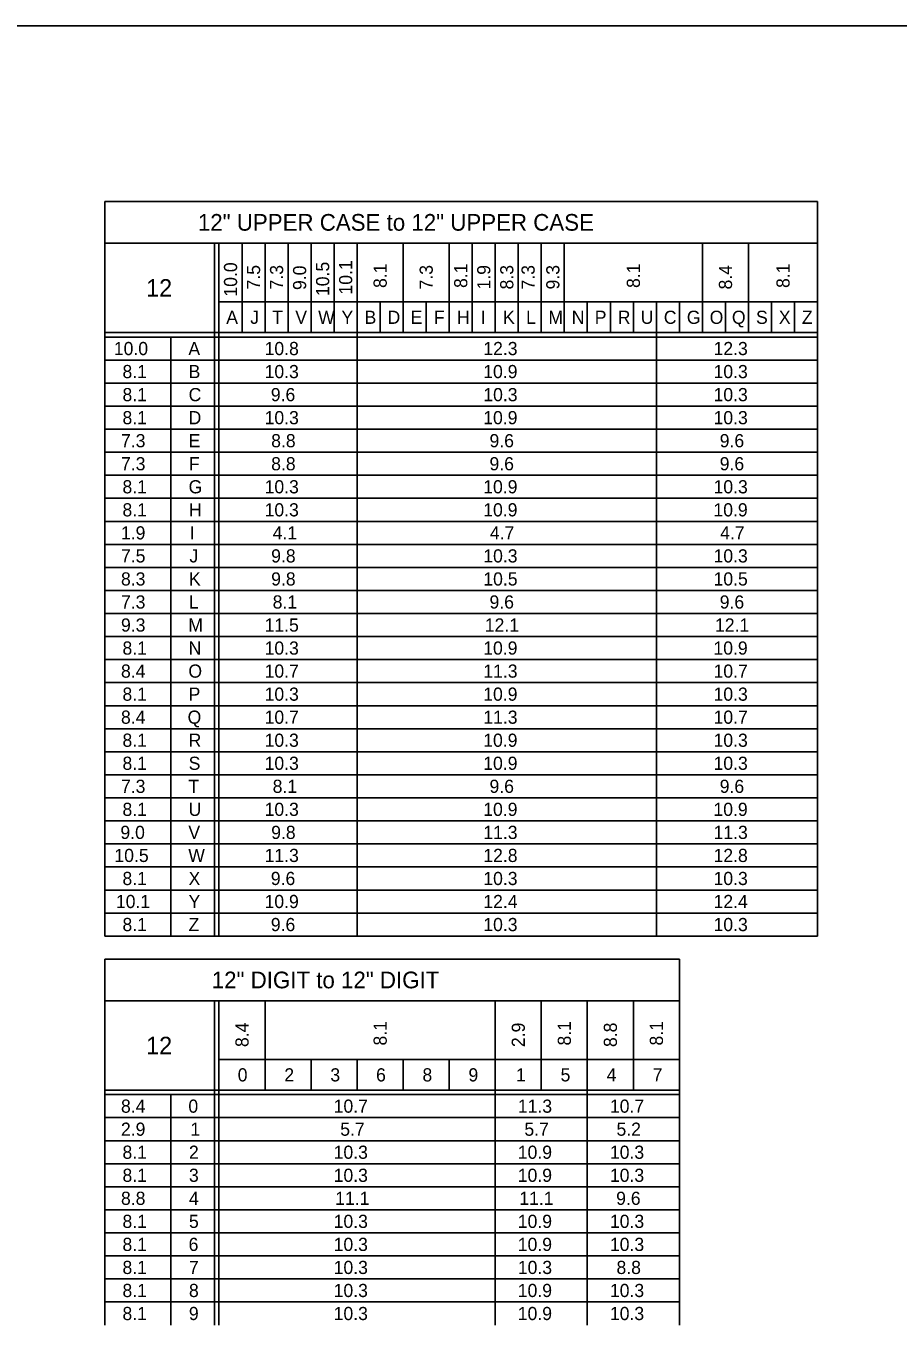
# Model space of a CAD drawing. Extents: x 638421 to 641849, y 297270 to 299646.
# Drawn here: x 640342.2 to 640541.1, y 298146.6 to 298442.6 of the extents above; entities that cross this region are included whole.
import ezdxf

# ---------------------------------------------------------------- set-up
doc = ezdxf.new("R2010")
doc.units = 0
doc.layers.add('1', color=7, linetype='Continuous')
doc.layers.add('2', color=7, linetype='Continuous')

msp = doc.modelspace()

# ---------------------------------------------------------------- linework, layer by layer
at = {"layer": '1'}
msp.add_line((640143.31, 298442.63), (640929.31, 298442.63), dxfattribs=at)
at = {"layer": '2'}
for p, q in [((640522.71, 298402.63), (640360.21, 298402.63)), ((640360.21, 298402.63), (640360.21, 298235.25)), ((640522.71, 298402.63), (640522.71, 298235.25)), ((640360.21, 298393.13), (640522.71, 298393.13)), ((640385.21, 298393.13), (640385.21, 298235.25)), ((640386.21, 298393.13), (640386.21, 298235.25)), ((640391.46, 298393.13), (640391.46, 298372.75)), ((640396.71, 298393.13), (640396.71, 298372.75)), ((640401.96, 298393.13), (640401.96, 298372.75)), ((640407.21, 298393.13), (640407.21, 298372.75)), ((640412.46, 298393.13), (640412.46, 298372.75)), ((640417.71, 298393.13), (640417.71, 298235.25)), ((640428.21, 298393.13), (640428.21, 298372.75)), ((640438.71, 298393.13), (640438.71, 298372.75)), ((640443.96, 298393.13), (640443.96, 298372.75)), ((640449.21, 298393.13), (640449.21, 298372.75)), ((640454.46, 298393.13), (640454.46, 298372.75)), ((640459.71, 298393.13), (640459.71, 298372.75)), ((640464.96, 298393.13), (640464.96, 298372.75)), ((640496.46, 298393.13), (640496.46, 298372.75)), ((640506.96, 298393.13), (640506.96, 298372.75)), ((640386.21, 298379.75), (640522.71, 298379.75)), ((640422.96, 298379.75), (640422.96, 298372.75)), ((640433.46, 298379.75), (640433.46, 298372.75)), ((640470.21, 298379.75), (640470.21, 298372.75)), ((640475.46, 298379.75), (640475.46, 298372.75)), ((640480.71, 298379.75), (640480.71, 298372.75)), ((640480.71, 298379.75), (640480.71, 298372.75)), ((640485.96, 298379.75), (640485.96, 298235.25)), ((640491.21, 298379.75), (640491.21, 298372.75)), ((640501.71, 298379.75), (640501.71, 298372.75)), ((640512.21, 298379.75), (640512.21, 298372.75)), ((640517.46, 298379.75), (640517.46, 298372.75)), ((640522.71, 298372.75), (640360.21, 298372.75)), ((640522.71, 298371.75), (640360.21, 298371.75)), ((640375.21, 298371.75), (640375.21, 298235.25)), ((640522.71, 298366.5), (640360.21, 298366.5)), ((640522.71, 298361.25), (640360.21, 298361.25)), ((640522.71, 298356), (640360.21, 298356)), ((640522.71, 298350.75), (640360.21, 298350.75)), ((640522.71, 298345.5), (640360.21, 298345.5)), ((640522.71, 298340.25), (640360.21, 298340.25)), ((640522.71, 298335), (640360.21, 298335)), ((640522.71, 298329.75), (640360.21, 298329.75)), ((640522.71, 298324.5), (640360.21, 298324.5)), ((640522.71, 298319.25), (640360.21, 298319.25)), ((640522.71, 298314), (640360.21, 298314)), ((640522.71, 298308.75), (640360.21, 298308.75)), ((640522.71, 298303.5), (640360.21, 298303.5)), ((640522.71, 298298.25), (640360.21, 298298.25)), ((640522.71, 298293), (640360.21, 298293)), ((640522.71, 298287.75), (640360.21, 298287.75)), ((640522.71, 298282.5), (640360.21, 298282.5)), ((640522.71, 298277.25), (640360.21, 298277.25)), ((640522.71, 298272), (640360.21, 298272)), ((640522.71, 298266.75), (640360.21, 298266.75)), ((640522.71, 298261.5), (640360.21, 298261.5)), ((640522.71, 298256.25), (640360.21, 298256.25)), ((640522.71, 298251), (640360.21, 298251)), ((640522.71, 298245.75), (640360.21, 298245.75)), ((640522.71, 298240.5), (640360.21, 298240.5)), ((640360.21, 298235.25), (640360.21, 298235.25)), ((640360.21, 298235.25), (640522.71, 298235.25)), ((640491.21, 298230), (640360.21, 298230)), ((640360.21, 298230), (640360.21, 298146.63)), ((640491.21, 298146.63), (640491.21, 298230)), ((640360.21, 298220.5), (640491.21, 298220.5)), ((640385.21, 298220.5), (640385.21, 298146.63)), ((640386.21, 298220.5), (640386.21, 298146.63)), ((640396.71, 298220.5), (640396.71, 298200.13)), ((640449.21, 298220.5), (640449.21, 298146.63)), ((640459.71, 298220.5), (640459.71, 298200.13)), ((640470.21, 298220.5), (640470.21, 298146.63)), ((640480.71, 298220.5), (640480.71, 298200.13)), ((640386.21, 298207.13), (640491.21, 298207.13)), ((640407.21, 298207.13), (640407.21, 298200.13)), ((640417.71, 298207.13), (640417.71, 298200.13)), ((640428.21, 298207.13), (640428.21, 298200.13)), ((640438.71, 298207.13), (640438.71, 298200.13)), ((640491.21, 298200.13), (640360.21, 298200.13)), ((640491.21, 298199.13), (640360.21, 298199.13)), ((640375.21, 298199.13), (640375.21, 298146.63)), ((640491.21, 298193.88), (640360.21, 298193.88)), ((640491.21, 298188.63), (640360.21, 298188.63)), ((640491.21, 298183.38), (640360.21, 298183.38)), ((640491.21, 298178.13), (640360.21, 298178.13)), ((640491.21, 298172.88), (640360.21, 298172.88)), ((640491.21, 298167.63), (640360.21, 298167.63)), ((640491.21, 298162.38), (640360.21, 298162.38)), ((640491.21, 298157.13), (640360.21, 298157.13)), ((640491.21, 298151.88), (640360.21, 298151.88))]:
    msp.add_line(p, q, dxfattribs=at)

# ---------------------------------------------------------------- texts
for s, height, p in [('12" UPPER CASE to 12" UPPER CASE', 3.8, (640381.4, 298395.98)), ('12', 4, (640369.58, 298380.94)), ('A', 3, (640387.86, 298374.75)), ('J', 3, (640393.34, 298374.75)), ('T', 3, (640398.34, 298374.75)), ('V', 3, (640403.61, 298374.75)), ('W', 3, (640408.83, 298374.75)), ('Y', 3, (640414.14, 298374.75)), ('B', 3, (640419.4, 298374.75)), ('D', 3, (640424.65, 298374.75)), ('E', 3, (640429.92, 298374.75)), ('F', 3, (640435.22, 298374.75)), ('H', 3, (640440.49, 298374.75)), ('I', 3, (640445.9, 298374.75)), ('K', 3, (640450.99, 298374.75)), ('L', 3, (640456.24, 298374.75)), ('M', 3, (640461.33, 298374.75)), ('N', 3, (640466.65, 298374.75)), ('P', 3, (640471.9, 298374.75)), ('R', 3, (640477.15, 298374.75)), ('U', 3, (640482.39, 298374.75)), ('C', 3, (640487.65, 298374.75)), ('G', 3, (640492.9, 298374.75)), ('O', 3, (640498.11, 298374.75)), ('Q', 3, (640503.18, 298374.75)), ('S', 3, (640508.67, 298374.75)), ('X', 3, (640513.89, 298374.75)), ('Z', 3, (640519.15, 298374.75)), ('10.0', 3, (640362.23, 298367.63)), ('A', 3, (640379.23, 298367.63)), ('10.8', 3, (640396.61, 298367.63)), ('12.3', 3, (640446.49, 298367.63)), ('12.3', 3, (640498.99, 298367.63)), ('8.1', 3, (640364.2, 298362.38)), ('B', 3, (640379.28, 298362.38)), ('10.3', 3, (640396.61, 298362.38)), ('10.9', 3, (640446.47, 298362.38)), ('10.3', 3, (640498.99, 298362.38)), ('8.1', 3, (640364.2, 298357.13)), ('C', 3, (640379.28, 298357.13)), ('9.6', 3, (640398.03, 298357.13)), ('10.3', 3, (640446.49, 298357.13)), ('10.3', 3, (640498.99, 298357.13)), ('8.1', 3, (640364.2, 298351.88)), ('D', 3, (640379.28, 298351.88)), ('10.3', 3, (640396.61, 298351.88)), ('10.9', 3, (640446.47, 298351.88)), ('10.3', 3, (640498.99, 298351.88)), ('7.3', 3, (640363.86, 298346.63)), ('E', 3, (640379.29, 298346.63)), ('8.8', 3, (640398.11, 298346.63)), ('9.6', 3, (640447.9, 298346.63)), ('9.6', 3, (640500.4, 298346.63)), ('7.3', 3, (640363.86, 298341.38)), ('F', 3, (640379.35, 298341.38)), ('8.8', 3, (640398.11, 298341.38)), ('9.6', 3, (640447.9, 298341.38)), ('9.6', 3, (640500.4, 298341.38)), ('8.1', 3, (640364.2, 298336.13)), ('G', 3, (640379.28, 298336.13)), ('10.3', 3, (640396.61, 298336.13)), ('10.9', 3, (640446.47, 298336.13)), ('10.3', 3, (640498.99, 298336.13)), ('8.1', 3, (640364.2, 298330.88)), ('H', 3, (640379.36, 298330.88)), ('10.3', 3, (640396.61, 298330.88)), ('10.9', 3, (640446.47, 298330.88)), ('10.9', 3, (640498.97, 298330.88)), ('1.9', 3, (640363.85, 298325.63)), ('I', 3, (640379.53, 298325.63)), ('4.1', 3, (640398.45, 298325.63)), ('4.7', 3, (640447.99, 298325.63)), ('4.7', 3, (640500.49, 298325.63)), ('7.5', 3, (640363.86, 298320.38)), ('J', 3, (640379.47, 298320.38)), ('9.8', 3, (640398.11, 298320.38)), ('10.3', 3, (640446.49, 298320.38)), ('10.3', 3, (640498.99, 298320.38)), ('8.3', 3, (640363.86, 298315.13)), ('K', 3, (640379.36, 298315.13)), ('9.8', 3, (640398.11, 298315.13)), ('10.5', 3, (640446.49, 298315.13)), ('10.5', 3, (640498.99, 298315.13)), ('7.3', 3, (640363.86, 298309.88)), ('L', 3, (640379.36, 298309.88)), ('8.1', 3, (640398.45, 298309.88)), ('9.6', 3, (640447.9, 298309.88)), ('9.6', 3, (640500.4, 298309.88)), ('9.3', 3, (640363.86, 298304.63)), ('M', 3, (640379.21, 298304.63)), ('11.5', 3, (640396.61, 298304.63)), ('12.1', 3, (640446.83, 298304.63)), ('12.1', 3, (640499.33, 298304.63)), ('8.1', 3, (640364.2, 298299.38)), ('N', 3, (640379.28, 298299.38)), ('10.3', 3, (640396.61, 298299.38)), ('10.9', 3, (640446.47, 298299.38)), ('10.9', 3, (640498.97, 298299.38)), ('8.4', 3, (640363.86, 298294.13)), ('O', 3, (640379.23, 298294.13)), ('10.7', 3, (640396.61, 298294.13)), ('11.3', 3, (640446.49, 298294.13)), ('10.7', 3, (640498.99, 298294.13)), ('8.1', 3, (640364.2, 298288.88)), ('P', 3, (640379.28, 298288.88)), ('10.3', 3, (640396.61, 298288.88)), ('10.9', 3, (640446.47, 298288.88)), ('10.3', 3, (640498.99, 298288.88)), ('8.4', 3, (640363.86, 298283.63)), ('Q', 3, (640379.05, 298283.63)), ('10.7', 3, (640396.61, 298283.63)), ('11.3', 3, (640446.49, 298283.63)), ('10.7', 3, (640498.99, 298283.63)), ('8.1', 3, (640364.2, 298278.38)), ('R', 3, (640379.28, 298278.38)), ('10.3', 3, (640396.61, 298278.38)), ('10.9', 3, (640446.47, 298278.38)), ('10.3', 3, (640498.99, 298278.38)), ('8.1', 3, (640364.2, 298273.13)), ('S', 3, (640379.29, 298273.13)), ('10.3', 3, (640396.61, 298273.13)), ('10.9', 3, (640446.47, 298273.13)), ('10.3', 3, (640498.99, 298273.13)), ('7.3', 3, (640363.86, 298267.88)), ('T', 3, (640379.22, 298267.88)), ('8.1', 3, (640398.45, 298267.88)), ('9.6', 3, (640447.9, 298267.88)), ('9.6', 3, (640500.4, 298267.88)), ('8.1', 3, (640364.2, 298262.63)), ('U', 3, (640379.27, 298262.63)), ('10.3', 3, (640396.61, 298262.63)), ('10.9', 3, (640446.47, 298262.63)), ('10.9', 3, (640498.97, 298262.63)), ('9.0', 3, (640363.73, 298257.38)), ('V', 3, (640379.23, 298257.38)), ('9.8', 3, (640398.11, 298257.38)), ('11.3', 3, (640446.49, 298257.38)), ('11.3', 3, (640498.99, 298257.38)), ('10.5', 3, (640362.36, 298252.13)), ('W', 3, (640379.21, 298252.13)), ('11.3', 3, (640396.61, 298252.13)), ('12.8', 3, (640446.49, 298252.13)), ('12.8', 3, (640498.99, 298252.13)), ('8.1', 3, (640364.2, 298246.88)), ('X', 3, (640379.27, 298246.88)), ('9.6', 3, (640398.03, 298246.88)), ('10.3', 3, (640446.49, 298246.88)), ('10.3', 3, (640498.99, 298246.88)), ('10.1', 3, (640362.7, 298241.63)), ('Y', 3, (640379.27, 298241.63)), ('10.9', 3, (640396.6, 298241.63)), ('12.4', 3, (640446.49, 298241.63)), ('12.4', 3, (640498.99, 298241.63)), ('8.1', 3, (640364.2, 298236.38)), ('Z', 3, (640379.28, 298236.38)), ('9.6', 3, (640398.03, 298236.38)), ('10.3', 3, (640446.49, 298236.38)), ('10.3', 3, (640498.99, 298236.38)), ('12" DIGIT to 12" DIGIT', 3.8, (640384.56, 298223.35)), ('12', 4, (640369.58, 298208.31)), ('0', 3, (640390.48, 298202.13)), ('2', 3, (640401.11, 298202.13)), ('3', 3, (640411.61, 298202.13)), ('6', 3, (640422.03, 298202.13)), ('8', 3, (640432.61, 298202.13)), ('9', 3, (640443.1, 298202.13)), ('1', 3, (640453.95, 298202.13)), ('5', 3, (640464.11, 298202.13)), ('4', 3, (640474.61, 298202.13)), ('7', 3, (640485.11, 298202.13)), ('8.4', 3, (640363.86, 298195)), ('0', 3, (640379.23, 298195)), ('10.7', 3, (640412.36, 298195)), ('11.3', 3, (640454.36, 298195)), ('10.7', 3, (640475.36, 298195)), ('2.9', 3, (640363.85, 298189.75)), ('1', 3, (640379.7, 298189.75)), ('5.7', 3, (640413.86, 298189.75)), ('5.7', 3, (640455.86, 298189.75)), ('5.2', 3, (640476.86, 298189.75)), ('8.1', 3, (640364.2, 298184.5)), ('2', 3, (640379.36, 298184.5)), ('10.3', 3, (640412.36, 298184.5)), ('10.9', 3, (640454.35, 298184.5)), ('10.3', 3, (640475.36, 298184.5)), ('8.1', 3, (640364.2, 298179.25)), ('3', 3, (640379.36, 298179.25)), ('10.3', 3, (640412.36, 298179.25)), ('10.9', 3, (640454.35, 298179.25)), ('10.3', 3, (640475.36, 298179.25)), ('8.8', 3, (640363.86, 298174)), ('4', 3, (640379.36, 298174)), ('11.1', 3, (640412.7, 298174)), ('11.1', 3, (640454.7, 298174)), ('9.6', 3, (640476.78, 298174)), ('8.1', 3, (640364.2, 298168.75)), ('5', 3, (640379.36, 298168.75)), ('10.3', 3, (640412.36, 298168.75)), ('10.9', 3, (640454.35, 298168.75)), ('10.3', 3, (640475.36, 298168.75)), ('8.1', 3, (640364.2, 298163.5)), ('6', 3, (640379.28, 298163.5)), ('10.3', 3, (640412.36, 298163.5)), ('10.9', 3, (640454.35, 298163.5)), ('10.3', 3, (640475.36, 298163.5)), ('8.1', 3, (640364.2, 298158.25)), ('7', 3, (640379.36, 298158.25)), ('10.3', 3, (640412.36, 298158.25)), ('10.3', 3, (640454.36, 298158.25)), ('8.8', 3, (640476.86, 298158.25)), ('8.1', 3, (640364.2, 298153)), ('8', 3, (640379.36, 298153)), ('10.3', 3, (640412.36, 298153)), ('10.9', 3, (640454.35, 298153)), ('10.3', 3, (640475.36, 298153)), ('8.1', 3, (640364.2, 298147.75)), ('9', 3, (640379.35, 298147.75)), ('10.3', 3, (640412.36, 298147.75)), ('10.9', 3, (640454.35, 298147.75)), ('10.3', 3, (640475.36, 298147.75))]:
    msp.add_text(s, height=height, dxfattribs=at).set_placement(p)
for s, p in [('10.1', (640416.59, 298381.43)), ('10.0', (640390.34, 298380.96)), ('7.5', (640395.59, 298382.59)), ('7.3', (640400.84, 298382.59)), ('9.0', (640406.09, 298382.46)), ('10.5', (640411.34, 298381.09)), ('8.1', (640424.46, 298382.93)), ('7.3', (640434.96, 298382.59)), ('8.1', (640442.84, 298382.93)), ('1.9', (640448.09, 298382.58)), ('8.3', (640453.34, 298382.59)), ('7.3', (640458.2, 298382.58)), ('9.3', (640463.84, 298382.59)), ('8.1', (640482.21, 298382.93)), ('8.4', (640503.21, 298382.59)), ('8.1', (640516.34, 298382.93)), ('8.4', (640392.96, 298209.96)), ('8.1', (640424.46, 298210.31)), ('2.9', (640455.96, 298209.95)), ('8.1', (640466.46, 298210.31)), ('8.8', (640476.96, 298209.96)), ('8.1', (640487.46, 298210.31))]:
    msp.add_text(s, height=3, rotation=90, dxfattribs=at).set_placement(p)

doc.saveas('drawing.dxf')
